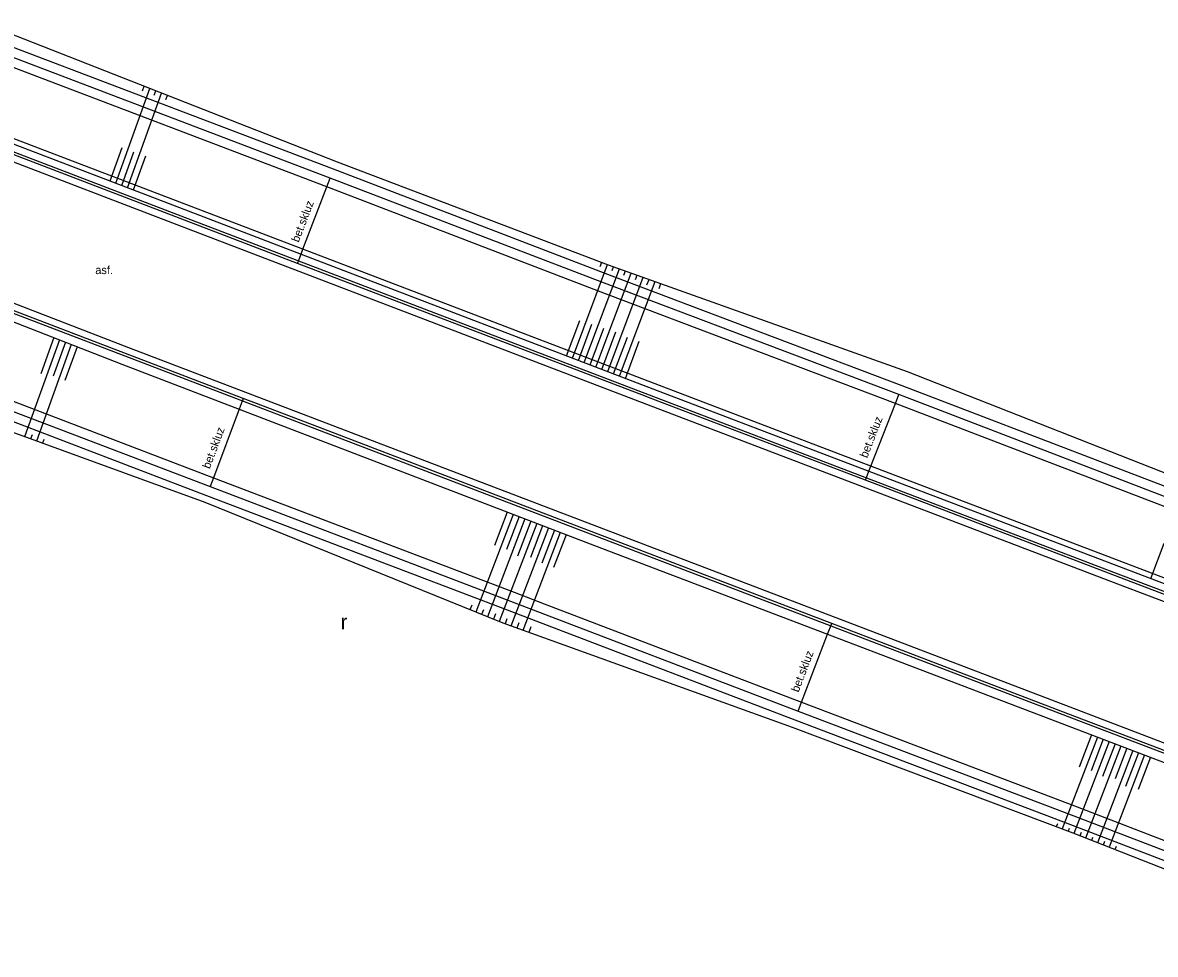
# Model space of a CAD drawing. Extents: x -541281 to -539153, y -1183881 to -1182141.
# Drawn here: x -539422.2 to -539332.2, y -1182469.4 to -1182395.4 of the extents above; entities that cross this region are included whole.
import ezdxf

# ---------------------------------------------------------------- set-up
doc = ezdxf.new("R2010")
doc.units = 0
for name, color, linetype in [('Vrstva 10', 7, 'Continuous'), ('Vrstva 11', 7, 'Continuous'), ('Vrstva 14', 7, 'Continuous'), ('Vrstva 15', 7, 'Continuous'), ('Vrstva 36', 7, 'Continuous'), ('Vrstva 40', 7, 'Continuous'), ('Vrstva 7', 7, 'Continuous'), ('Vrstva 9', 7, 'Continuous')]:
    doc.layers.add(name, color=color, linetype=linetype)

msp = doc.modelspace()

# ---------------------------------------------------------------- linework, layer by layer
at = {"layer": 'Vrstva 10'}
for p, q in [((-539447.295, -1182397.1), (-539409.948, -1182411.403)), ((-539413.744, -1182421.197), (-539451.102, -1182406.873)), ((-539409.948, -1182411.403), (-539372.649, -1182425.674)), ((-539376.393, -1182435.474), (-539413.744, -1182421.197)), ((-539372.649, -1182425.674), (-539335.258, -1182439.945)), ((-539339.016, -1182449.749), (-539376.393, -1182435.474)), ((-539335.258, -1182439.945), (-539297.88, -1182454.193)), ((-539301.621, -1182464.028), (-539339.016, -1182449.749))]:
    msp.add_line(p, q, dxfattribs=at)
at = {"layer": 'Vrstva 11'}
for p, q in [((-539409.677, -1182410.93), (-539447.039, -1182396.642)), ((-539397.506, -1182407.025), (-539422.999, -1182397.316)), ((-539398.042, -1182408.427), (-539423.633, -1182398.68)), ((-539414.01, -1182421.648), (-539451.174, -1182407.431)), ((-539375.926, -1182415.292), (-539397.506, -1182407.025)), ((-539376.46, -1182416.694), (-539398.042, -1182408.427)), ((-539369.143, -1182417.858), (-539375.926, -1182415.292)), ((-539369.808, -1182419.21), (-539376.46, -1182416.694)), ((-539352.341, -1182424.213), (-539369.143, -1182417.858)), ((-539352.875, -1182425.615), (-539369.808, -1182419.21)), ((-539432.11, -1182421.95), (-539407.044, -1182431.525)), ((-539432.647, -1182423.351), (-539407.578, -1182432.927)), ((-539325.348, -1182434.576), (-539352.341, -1182424.213)), ((-539372.482, -1182425.151), (-539372.688, -1182425.072)), ((-539325.882, -1182435.978), (-539352.875, -1182425.615)), ((-539377.808, -1182435.492), (-539399.16, -1182427.327)), ((-539407.044, -1182431.525), (-539383.17, -1182440.623)), ((-539407.578, -1182432.927), (-539383.704, -1182442.025)), ((-539376.492, -1182435.995), (-539377.808, -1182435.492)), ((-539383.17, -1182440.623), (-539380.779, -1182441.537)), ((-539383.704, -1182442.025), (-539381.444, -1182442.889)), ((-539380.779, -1182441.537), (-539360.332, -1182449.357)), ((-539381.444, -1182442.889), (-539360.866, -1182450.759)), ((-539360.332, -1182449.357), (-539338.441, -1182457.667)), ((-539360.866, -1182450.759), (-539338.977, -1182459.069)), ((-539338.441, -1182457.667), (-539313.706, -1182467.201)), ((-539338.977, -1182459.069), (-539314.244, -1182468.601))]:
    msp.add_line(p, q, dxfattribs=at)
for points in [[(-539372.688, -1182425.072), (-539400.353, -1182414.495), (-539409.677, -1182410.93)], [(-539399.16, -1182427.327), (-539403.841, -1182425.537), (-539404.681, -1182425.216), (-539414.01, -1182421.648)], [(-539335.056, -1182439.436), (-539355.267, -1182431.722), (-539372.482, -1182425.151)], [(-539339.187, -1182450.275), (-539357.945, -1182443.095), (-539376.492, -1182435.995)], [(-539297.727, -1182453.687), (-539306.804, -1182450.222), (-539335.056, -1182439.436)], [(-539301.798, -1182464.518), (-539311.302, -1182460.897), (-539339.187, -1182450.275)]]:
    msp.add_lwpolyline(points, dxfattribs=at)
at = {"layer": 'Vrstva 14'}
for p, q in [((-539446.729, -1182395.931), (-539409.381, -1182410.193)), ((-539425.391, -1182395.374), (-539397.219, -1182406.436)), ((-539397.774, -1182407.726), (-539423.361, -1182397.981)), ((-539397.219, -1182406.436), (-539375.687, -1182414.61)), ((-539376.193, -1182415.993), (-539397.774, -1182407.726)), ((-539409.381, -1182410.193), (-539400.073, -1182413.761)), ((-539400.073, -1182413.761), (-539372.148, -1182424.464)), ((-539375.687, -1182414.61), (-539351.949, -1182423.078)), ((-539352.608, -1182424.914), (-539376.193, -1182415.993)), ((-539432.336, -1182422.667), (-539407.311, -1182432.226)), ((-539351.949, -1182423.078), (-539325.164, -1182433.64)), ((-539407.69, -1182433.495), (-539436.094, -1182423.153)), ((-539372.148, -1182424.464), (-539354.984, -1182430.997)), ((-539325.615, -1182435.277), (-539352.608, -1182424.914)), ((-539404.681, -1182425.216), (-539405.005, -1182426.081)), ((-539407.311, -1182432.226), (-539383.437, -1182441.324)), ((-539384.021, -1182443.086), (-539407.69, -1182433.495)), ((-539383.437, -1182441.324), (-539360.599, -1182450.058)), ((-539361.048, -1182451.358), (-539384.021, -1182443.086)), ((-539358.275, -1182443.96), (-539357.945, -1182443.095)), ((-539360.599, -1182450.058), (-539338.709, -1182458.368)), ((-539338.778, -1182459.747), (-539361.048, -1182451.358)), ((-539338.709, -1182458.368), (-539313.975, -1182467.901)), ((-539314.443, -1182469.381), (-539338.778, -1182459.747))]:
    msp.add_line(p, q, dxfattribs=at)
for points in [[(-539400.353, -1182414.495), (-539400.073, -1182413.761), (-539399.927, -1182413.378), (-539398.042, -1182408.427), (-539397.774, -1182407.726)], [(-539451.44, -1182407.999), (-539451.41, -1182408.011), (-539414.325, -1182422.504)], [(-539414.325, -1182422.504), (-539405.005, -1182426.081), (-539376.773, -1182436.915)], [(-539355.267, -1182431.722), (-539354.984, -1182430.997), (-539354.83, -1182430.602), (-539352.875, -1182425.615), (-539352.608, -1182424.914)], [(-539405.005, -1182426.081), (-539407.044, -1182431.525), (-539407.311, -1182432.226)], [(-539354.984, -1182430.997), (-539306.505, -1182449.448), (-539297.285, -1182452.957)], [(-539376.773, -1182436.915), (-539358.275, -1182443.96), (-539311.619, -1182461.728), (-539301.862, -1182465.444)], [(-539360.599, -1182450.058), (-539360.332, -1182449.357), (-539358.275, -1182443.96)]]:
    msp.add_lwpolyline(points, dxfattribs=at)
at = {"layer": 'Vrstva 15'}
for p, q in [((-539414.785, -1182408.129), (-539412.082, -1182400.6)), ((-539412.68, -1182400.787), (-539412.547, -1182400.417)), ((-539413.85, -1182408.486), (-539411.15, -1182400.966)), ((-539411.745, -1182401.142), (-539411.616, -1182400.783)), ((-539410.806, -1182401.485), (-539410.685, -1182401.148)), ((-539415.252, -1182407.951), (-539414.294, -1182405.284)), ((-539414.318, -1182408.308), (-539413.362, -1182405.644)), ((-539413.384, -1182408.665), (-539412.413, -1182405.959)), ((-539378.53, -1182422.018), (-539375.742, -1182414.589)), ((-539377.595, -1182422.376), (-539374.8, -1182414.927)), ((-539376.331, -1182414.736), (-539376.209, -1182414.412)), ((-539375.389, -1182415.073), (-539375.271, -1182414.759)), ((-539376.661, -1182422.734), (-539373.857, -1182415.263)), ((-539375.728, -1182423.092), (-539372.916, -1182415.598)), ((-539374.793, -1182423.45), (-539371.973, -1182415.935)), ((-539374.456, -1182415.433), (-539374.329, -1182415.095)), ((-539373.52, -1182415.784), (-539373.387, -1182415.43)), ((-539372.611, -1182416.21), (-539372.445, -1182415.767)), ((-539371.645, -1182416.48), (-539371.503, -1182416.103)), ((-539378.996, -1182421.839), (-539377.944, -1182419.036)), ((-539378.062, -1182422.197), (-539376.988, -1182419.334)), ((-539419.725, -1182420.394), (-539420.755, -1182423.257)), ((-539377.128, -1182422.555), (-539376.035, -1182419.641)), ((-539376.195, -1182422.913), (-539375.081, -1182419.945)), ((-539375.261, -1182423.271), (-539374.169, -1182420.361)), ((-539419.258, -1182420.576), (-539422.029, -1182428.274)), ((-539418.327, -1182420.94), (-539421.091, -1182428.616)), ((-539418.793, -1182420.758), (-539419.762, -1182423.449)), ((-539417.861, -1182421.122), (-539418.829, -1182423.81)), ((-539374.327, -1182423.629), (-539373.223, -1182420.686)), ((-539421.438, -1182428.106), (-539421.56, -1182428.445)), ((-539420.51, -1182428.48), (-539420.62, -1182428.787)), ((-539383.234, -1182434.435), (-539386.203, -1182442.202)), ((-539382.301, -1182434.794), (-539385.276, -1182442.577)), ((-539383.701, -1182434.256), (-539384.71, -1182436.895)), ((-539382.768, -1182434.614), (-539383.766, -1182437.226)), ((-539381.367, -1182435.152), (-539384.349, -1182442.953)), ((-539380.434, -1182435.51), (-539383.413, -1182443.305)), ((-539381.834, -1182434.973), (-539382.894, -1182437.746)), ((-539380.9, -1182435.331), (-539381.87, -1182437.87)), ((-539379.967, -1182435.689), (-539380.97, -1182438.313)), ((-539379.5, -1182435.868), (-539382.472, -1182443.644)), ((-539379.033, -1182436.048), (-539380.033, -1182438.663)), ((-539332.596, -1182439.518), (-539331.54, -1182436.714)), ((-539386.525, -1182441.645), (-539386.666, -1182442.014)), ((-539385.599, -1182442.022), (-539385.74, -1182442.39)), ((-539384.648, -1182442.336), (-539384.812, -1182442.765)), ((-539383.728, -1182442.732), (-539383.883, -1182443.136)), ((-539382.777, -1182443.043), (-539382.942, -1182443.474)), ((-539381.835, -1182443.378), (-539382.001, -1182443.813)), ((-539336.847, -1182452.12), (-539339.642, -1182459.422)), ((-539335.912, -1182452.476), (-539338.706, -1182459.775)), ((-539337.315, -1182451.942), (-539338.298, -1182454.511)), ((-539334.978, -1182452.832), (-539337.777, -1182460.143)), ((-539336.38, -1182452.298), (-539337.338, -1182454.8)), ((-539335.445, -1182452.654), (-539336.439, -1182455.251)), ((-539334.044, -1182453.188), (-539336.847, -1182460.511)), ((-539333.109, -1182453.544), (-539335.917, -1182460.88)), ((-539334.511, -1182453.01), (-539335.444, -1182455.448)), ((-539333.576, -1182453.366), (-539334.606, -1182456.057)), ((-539332.641, -1182453.722), (-539333.62, -1182456.279)), ((-539340.019, -1182459.008), (-539340.11, -1182459.245)), ((-539339.096, -1182459.393), (-539339.174, -1182459.598)), ((-539338.14, -1182459.693), (-539338.242, -1182459.959)), ((-539337.228, -1182460.108), (-539337.312, -1182460.327)), ((-539336.27, -1182460.404), (-539336.382, -1182460.696)), ((-539335.353, -1182460.806), (-539335.452, -1182461.064))]:
    msp.add_line(p, q, dxfattribs=at)
at = {"layer": 'Vrstva 7'}
for p, q in [((-539399.927, -1182413.378), (-539446.569, -1182395.555)), ((-539371.968, -1182424.062), (-539399.927, -1182413.378)), ((-539354.83, -1182430.602), (-539371.968, -1182424.062))]:
    msp.add_line(p, q, dxfattribs=at)
msp.add_lwpolyline([(-539297.225, -1182452.584), (-539306.369, -1182449.095), (-539354.83, -1182430.602)], dxfattribs=at)
at = {"layer": 'Vrstva 9'}
for p, q in [((-539409.606, -1182410.743), (-539446.968, -1182396.455)), ((-539451.245, -1182407.618), (-539414.081, -1182421.835)), ((-539372.411, -1182424.964), (-539409.606, -1182410.743)), ((-539414.081, -1182421.835), (-539376.563, -1182436.182)), ((-539334.985, -1182439.249), (-539372.411, -1182424.964)), ((-539376.563, -1182436.182), (-539339.258, -1182450.462)), ((-539297.656, -1182453.5), (-539334.985, -1182439.249)), ((-539339.258, -1182450.462), (-539301.869, -1182464.705))]:
    msp.add_line(p, q, dxfattribs=at)

# ---------------------------------------------------------------- texts
at = {"layer": 'Vrstva 36'}
msp.add_text('r', height=1.2, dxfattribs=at).set_placement((-539396.936, -1182443.572))
at = {"layer": 'Vrstva 40'}
for rotation, p in [(69.14308, (-539400.268, -1182412.868)), (68.66588, (-539355.132, -1182430.001)), (69.435, (-539407.333, -1182430.859)), (69.13527, (-539360.582, -1182448.61))]:
    msp.add_text('bet.skluz', height=0.65, rotation=rotation, dxfattribs=at).set_placement(p)
msp.add_text('asf.', height=0.65, dxfattribs=at).set_placement((-539416.419, -1182415.348))

doc.saveas('drawing.dxf')
